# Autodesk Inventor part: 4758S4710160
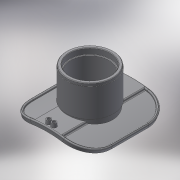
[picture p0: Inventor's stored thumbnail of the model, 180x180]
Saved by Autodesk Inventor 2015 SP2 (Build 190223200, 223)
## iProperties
Created: 2017-08
Part Number: 4758S4710160
Material: Generic
Description: PLASSON WASTEWATER SADDLE 560-710X160 SPIGOT INLET
Document SubType Name: Modeling
Designer: Кирилл
Density: 1 g/cm^3
Appearance: Default
Author: Кирилл
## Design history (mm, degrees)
derived "4758S4.ipt"
feature "Solid1::4758S4.ipt"
feature "Solid2::4758S4.ipt"
feature "Solid3::4758S4.ipt"
tag "TaggingFeature1"
body "Solid1"
other parameters: "d1" = 277, "d2" = 738.4, "d4" = 0, "d5" = 83.1, "d6" = 8, "d7" = 15 deg, "d8" = 7.5 deg, "d10" = 0, "d11" = 461.5, "d38" = 3.55, "d40" = 381, "d41" = 15, "d42" = 130.5, "d43" = 17.6, "d44" = 8.8, "d46" = 5 deg, "d47" = 4, "d49" = 4, "d51" = 14, "d52" = 0, "d53" = 3, "d54" = 0, "d75" = 0, "d77" = 0, "d78" = 1.6, "d82" = 125, "d84" = 156.8, "d85" = 128, "d86" = 136, "d87" = 18.75, "d88" = 152, "d89" = 18.75, "d90" = 9.375, "d91" = 1.6, "B_" = 277, "H_" = 125
